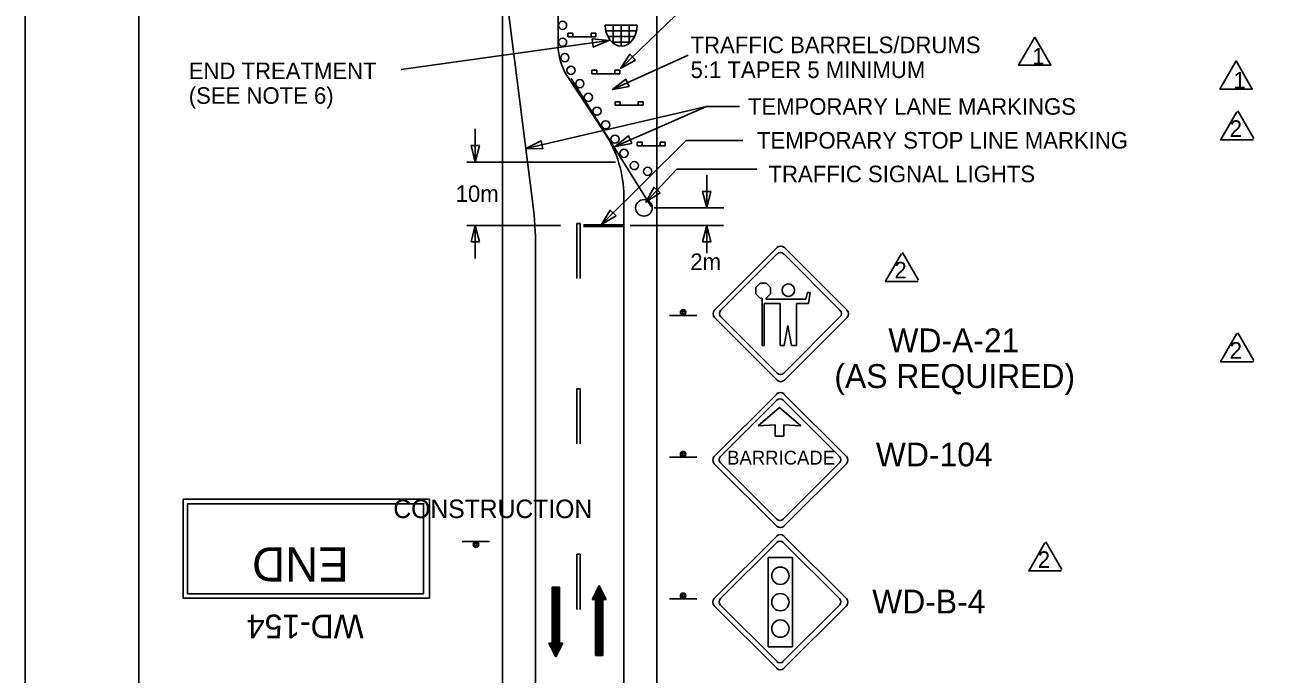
# Model space of a CAD drawing. Extents: x 2179 to 2395, y 134 to 413.
# Drawn here: x 2178.7 to 2288.3, y 251.3 to 308.2 of the extents above; entities that cross this region are included whole.
import ezdxf

# ---------------------------------------------------------------- set-up
doc = ezdxf.new("R2010")
doc.units = 0
for name, color, linetype in [('Level 1', 7, 'Continuous'), ('Level 10', 7, 'Continuous'), ('Level 2', 7, 'Continuous'), ('Level 4', 7, 'Continuous'), ('Level 44', 7, 'Continuous'), ('Level 5', 7, 'Continuous'), ('Level 60', 7, 'Continuous'), ('Level 63', 7, 'Continuous')]:
    doc.layers.add(name, color=color, linetype=linetype)

# ---------------------------------------------------------------- blocks, each defined once
blk = doc.blocks.new('END')
at = {"layer": 'Level 2'}
for points in [[(0, 8.676), (21.598, 8.676), (21.598, 0), (0, 0)], [(0.511, 8.287), (21.224, 8.287), (21.224, 0.397), (0.511, 0.397)]]:
    blk.add_lwpolyline(points, close=True, dxfattribs=at)
at = {"layer": 'Level 44'}
for s, height, rotation, p in [('END', 3, 359.99999, (7.085, 4.219)), ('CONSTRUCTION', 1.62, 179.99999, (3.164, 1.653))]:
    blk.add_text(s, height=height, rotation=rotation, dxfattribs=at).set_placement(p)
blk = doc.blocks.new('REV1')
at = {"layer": 'Level 1'}
blk.add_lwpolyline([(0.114, 1.689), (-1.305, -0.781), (1.533, -0.781)], close=True, dxfattribs=at)
blk.add_text('1', height=1.448, rotation=360, dxfattribs=at).set_placement((-0.113, -0.724))

msp = doc.modelspace()

# ---------------------------------------------------------------- linework, layer by layer
at = {"layer": 'Level 1'}
for p, q in [((2243.25, 285.56), (2242.87, 285.18)), ((2242.87, 285.18), (2242.87, 284.63)), ((2243.79, 285.56), (2243.25, 285.56)), ((2244.17, 285.18), (2243.79, 285.56)), ((2244.17, 284.63), (2244.17, 285.18)), ((2242.87, 284.63), (2243.25, 284.25)), ((2243.25, 284.25), (2243.42, 284.25)), ((2243.42, 284.25), (2243.42, 280.1)), ((2243.79, 284.25), (2244.17, 284.63)), ((2243.79, 284.18), (2243.79, 284.25)), ((2247.27, 284.18), (2243.79, 284.18)), ((2247.41, 284.76), (2247.27, 284.18)), ((2247.65, 284.76), (2247.41, 284.76)), ((2247.49, 283.79), (2247.65, 284.76)), ((2243.61, 280.1), (2243.61, 283.79)), ((2243.61, 283.79), (2245, 283.79)), ((2245, 283.79), (2245, 280.1)), ((2246.44, 280.1), (2246.44, 283.79)), ((2246.44, 283.79), (2247.49, 283.79)), ((2245.36, 280.1), (2245.69, 281.87)), ((2245.69, 281.87), (2246, 280.1)), ((2243.42, 280.1), (2243.61, 280.1)), ((2245, 280.1), (2245.36, 280.1)), ((2246, 280.1), (2246.44, 280.1)), ((2243.95, 261.5), (2246.11, 261.5)), ((2243.95, 253.67), (2243.95, 261.5)), ((2243.95, 253.68), (2243.95, 261.5)), ((2246.11, 261.5), (2246.11, 253.68)), ((2246.11, 253.68), (2243.95, 253.68)), ((2243.95, 253.68), (2243.95, 253.67))]:
    msp.add_line(p, q, dxfattribs=at)
msp.add_circle((2245.73, 284.96), 0.544, dxfattribs=at)
at = {"layer": 'Level 10'}
for p, q in [((2231.01, 304.4), (2256.5, 329.05)), ((2234.19, 178.24), (2234.19, 326.61)), ((2220.64, 178.24), (2220.64, 313.63)), ((2225.53, 313.63), (2225.53, 306.46)), ((2223.31, 292.52), (2221.04, 310.52)), ((2229.99, 306.85), (2211.76, 304.33)), ((2230.29, 302.55), (2236.95, 305.57)), ((2226.35, 303.71), (2229.65, 298.7)), ((2226.66, 303.54), (2233.7, 292.29)), ((2222.7, 297.38), (2238.55, 301.08)), ((2230.53, 297.57), (2238.55, 301.08)), ((2241.46, 301.08), (2238.55, 301.08)), ((2218.26, 299.1), (2218.26, 296.2)), ((2229.33, 290.71), (2236.77, 298.09)), ((2236.77, 298.09), (2241.75, 298.09)), ((2230.56, 296.2), (2217.53, 296.2)), ((2233.22, 292.69), (2235.94, 295.56)), ((2235.94, 295.56), (2242.97, 295.56)), ((2238.57, 295.06), (2238.57, 292.18)), ((2231.29, 178.24), (2231.29, 293.21)), ((2233.95, 292.18), (2240.06, 292.18)), ((2225.73, 290.64), (2217.53, 290.64)), ((2218.26, 287.74), (2218.26, 290.64)), ((2231.29, 290.69), (2227.75, 290.69)), ((2231.29, 290.69), (2227.75, 290.69)), ((2231.29, 290.64), (2227.75, 290.64)), ((2231.29, 290.64), (2227.75, 290.64)), ((2231.29, 290.64), (2227.75, 290.64)), ((2231.29, 290.6), (2227.75, 290.6)), ((2231.29, 290.6), (2227.75, 290.6)), ((2231.29, 290.55), (2227.75, 290.55)), ((2240.04, 290.64), (2231.85, 290.64)), ((2238.57, 290.64), (2238.57, 288.2)), ((2223.55, 178.24), (2223.55, 288.76)), ((2225.02, 254), (2225.02, 258.91)), ((2225.64, 258.91), (2225.02, 258.91)), ((2225.02, 253.39), (2225.02, 258.91)), ((2225.1, 253.24), (2225.1, 258.91)), ((2225.18, 253.08), (2225.18, 258.91)), ((2225.25, 252.93), (2225.25, 258.91)), ((2225.33, 252.78), (2225.33, 258.91)), ((2225.41, 252.93), (2225.41, 258.91)), ((2225.48, 253.08), (2225.48, 258.91)), ((2225.56, 253.24), (2225.56, 258.91)), ((2225.64, 254), (2225.64, 258.91)), ((2225.64, 253.39), (2225.64, 258.91)), ((2229.13, 259.05), (2228.52, 257.82)), ((2228.97, 258.74), (2228.97, 252.91)), ((2229.05, 258.89), (2229.05, 252.91)), ((2229.13, 259.05), (2229.13, 252.91)), ((2229.13, 259.05), (2229.74, 257.82)), ((2229.21, 258.89), (2229.21, 252.91)), ((2229.28, 258.74), (2229.28, 252.91)), ((2228.52, 257.82), (2228.82, 257.82)), ((2228.59, 257.97), (2228.59, 257.82)), ((2228.67, 258.13), (2228.67, 257.82)), ((2228.75, 258.28), (2228.75, 257.82)), ((2228.82, 258.43), (2228.82, 252.91)), ((2228.82, 257.82), (2228.82, 252.91)), ((2228.9, 258.59), (2228.9, 252.91)), ((2229.36, 258.59), (2229.36, 252.91)), ((2229.44, 258.43), (2229.44, 252.91)), ((2229.44, 257.82), (2229.44, 252.91)), ((2229.44, 257.82), (2229.74, 257.82)), ((2229.51, 258.28), (2229.51, 257.82)), ((2229.59, 258.13), (2229.59, 257.82)), ((2229.67, 257.97), (2229.67, 257.82)), ((2225.33, 252.78), (2224.72, 254)), ((2225.02, 254), (2224.72, 254)), ((2224.79, 253.85), (2224.79, 254)), ((2224.87, 253.7), (2224.87, 254)), ((2224.95, 253.54), (2224.95, 254)), ((2225.33, 252.78), (2225.94, 254)), ((2225.94, 254), (2225.64, 254)), ((2225.71, 253.54), (2225.71, 254)), ((2225.79, 253.7), (2225.79, 254)), ((2225.87, 253.85), (2225.87, 254)), ((2228.82, 252.91), (2229.44, 252.91))]:
    msp.add_line(p, q, dxfattribs=at)
for points in [[(2228.51, 307.01), (2229.99, 306.85), (2228.61, 306.29)], [(2232.31, 305.13), (2231.01, 304.4), (2231.81, 305.66)], [(2232, 297.82), (2230.53, 297.57), (2231.71, 298.49)], [(2218.62, 297.65), (2218.26, 296.2), (2217.9, 297.65)], [(2224.19, 297.36), (2222.7, 297.38), (2224.03, 298.06)], [(2234.48, 293.49), (2233.22, 292.69), (2233.95, 293.99)], [(2230.61, 291.48), (2229.33, 290.71), (2230.1, 291.99)], [(2217.9, 289.19), (2218.26, 290.64), (2218.62, 289.19)], [(2238.21, 289.19), (2238.57, 290.64), (2238.93, 289.19)]]:
    msp.add_lwpolyline(points, close=True, dxfattribs=at)
for centre in [(2225.92, 308.19), (2225.92, 306.71), (2226.12, 305.35), (2226.66, 304.24), (2227.44, 303.07), (2228.18, 301.87), (2228.94, 300.66), (2229.7, 299.46), (2230.52, 298.21), (2231.31, 296.96), (2232.21, 295.89), (2233.38, 295.38)]:
    msp.add_circle(centre, 0.359, dxfattribs=at)
msp.add_arc((2221.29, 293.21), 10, 0, 33.3066, dxfattribs=at)
at = {"layer": 'Level 2'}
for p, q in [((2227.17, 290.82), (2227.17, 285.98)), ((2227.46, 290.82), (2227.17, 290.82)), ((2227.46, 285.98), (2227.46, 290.82)), ((2227.17, 276.31), (2227.17, 271.47)), ((2227.46, 276.31), (2227.17, 276.31)), ((2227.46, 271.47), (2227.46, 276.31)), ((2227.17, 261.79), (2227.17, 256.96)), ((2227.46, 261.79), (2227.17, 261.79)), ((2227.46, 256.96), (2227.46, 261.79))]:
    msp.add_line(p, q, dxfattribs=at)
for points in [[(2214.24, 257.94), (2192.64, 257.94), (2192.64, 266.62), (2214.24, 266.62)], [(2213.72, 258.33), (2193.01, 258.33), (2193.01, 266.22), (2213.72, 266.22)]]:
    msp.add_lwpolyline(points, close=True, dxfattribs=at)
at = {"layer": 'Level 4'}
for p, q in [((2229.67, 308.21), (2232.47, 308.21)), ((2230.37, 308.21), (2230.37, 306.61)), ((2231.07, 308.21), (2231.07, 306.37)), ((2231.77, 308.21), (2231.77, 306.61)), ((2229.72, 307.71), (2232.42, 307.71)), ((2229.89, 307.21), (2232.25, 307.21)), ((2230.26, 306.71), (2231.88, 306.71))]:
    msp.add_line(p, q, dxfattribs=at)
msp.add_ellipse((2231.07, 308.22), major_axis=(0, -1.85), ratio=0.758621, start_param=4.716532, end_param=7.849839, dxfattribs=at)
at = {"layer": 'Level 44'}
for p, q in [((2244.74, 288.69), (2239.25, 283.2)), ((2250.88, 283.2), (2245.39, 288.69)), ((2239.8, 283.2), (2244.74, 288.14)), ((2245.33, 288.14), (2250.26, 283.2)), ((2235.29, 282.75), (2237.69, 282.75)), ((2239.25, 282.55), (2244.74, 277.06)), ((2239.25, 282.55), (2239.25, 282.55)), ((2244.74, 277.67), (2239.8, 282.61)), ((2250.26, 282.61), (2245.33, 277.67)), ((2245.39, 277.06), (2250.88, 282.55)), ((2244.71, 275.85), (2239.23, 270.38)), ((2239.78, 270.38), (2244.71, 275.3)), ((2245.29, 275.3), (2250.21, 270.38)), ((2250.82, 270.38), (2245.35, 275.85)), ((2244.95, 274.66), (2243.07, 273.07)), ((2246.83, 273.07), (2244.95, 274.66)), ((2243.07, 273.07), (2244.57, 273.15)), ((2244.57, 273.15), (2244.57, 272.15)), ((2245.33, 272.15), (2245.33, 273.15)), ((2245.33, 273.15), (2246.83, 273.07)), ((2244.57, 272.15), (2245.32, 272.15)), ((2235.29, 270.31), (2237.69, 270.31)), ((2239.23, 269.73), (2244.71, 264.26)), ((2239.23, 269.73), (2239.23, 269.73)), ((2244.71, 264.87), (2239.78, 269.8)), ((2250.21, 269.8), (2245.29, 264.87)), ((2245.35, 264.26), (2250.82, 269.73)), ((2244.71, 263.38), (2239.23, 257.92)), ((2250.82, 257.92), (2245.35, 263.38)), ((2217.12, 262.91), (2219.51, 262.91)), ((2239.78, 257.91), (2244.71, 262.83)), ((2245.29, 262.83), (2250.21, 257.91)), ((2235.29, 257.88), (2237.69, 257.88)), ((2239.23, 257.27), (2244.71, 251.79)), ((2239.23, 257.27), (2239.23, 257.27)), ((2244.71, 252.4), (2239.78, 257.33)), ((2250.21, 257.33), (2245.29, 252.4)), ((2245.35, 251.79), (2250.82, 257.27))]:
    msp.add_line(p, q, dxfattribs=at)
for centre, radius in [((2233.06, 292.18), 0.726), ((2236.5, 283.02), 0.24), ((2236.5, 283.02), 0.12), ((2236.5, 270.58), 0.24), ((2236.5, 270.58), 0.12), ((2218.32, 262.64), 0.24), ((2218.32, 262.64), 0.12), ((2245.03, 259.91), 0.76), ((2236.5, 258.15), 0.24), ((2236.5, 258.15), 0.12), ((2245.03, 257.59), 0.76), ((2245.03, 255.27), 0.76)]:
    msp.add_circle(centre, radius, dxfattribs=at)
for centre, radius, start, end in [((2245.06, 288.37), 0.459, 45, 135), ((2245.03, 287.84), 0.413, 45, 135), ((2239.58, 282.88), 0.459, 135, 225), ((2240.09, 282.9), 0.413, 135, 225), ((2249.97, 282.9), 0.413, 315, 45), ((2250.55, 282.88), 0.459, 315, 45), ((2245.03, 277.97), 0.413, 225, 315), ((2245.06, 277.39), 0.459, 225, 315), ((2245.03, 275.53), 0.458, 45, 135), ((2245, 275.01), 0.412, 45, 135), ((2239.56, 270.06), 0.458, 135, 225), ((2240.07, 270.09), 0.412, 135, 225), ((2249.92, 270.09), 0.412, 315, 45), ((2250.5, 270.06), 0.458, 315, 45), ((2245, 265.16), 0.412, 225, 315), ((2245.03, 264.59), 0.458, 225, 315), ((2245.03, 263.06), 0.458, 45, 135), ((2245, 262.54), 0.412, 45, 135), ((2239.56, 257.59), 0.458, 135, 225), ((2240.07, 257.62), 0.412, 135, 225), ((2249.92, 257.62), 0.412, 315, 45), ((2250.5, 257.59), 0.458, 315, 45), ((2245, 252.69), 0.412, 225, 315), ((2245.03, 252.12), 0.458, 225, 315)]:
    msp.add_arc(centre, radius, start, end, dxfattribs=at)
at = {"layer": 'Level 5'}
for p, q in [((2226.83, 307.5), (2226.39, 307.5)), ((2226.39, 307.5), (2226.39, 307.19)), ((2226.39, 307.19), (2228.85, 307.19)), ((2226.83, 307.19), (2226.83, 307.5)), ((2228.85, 307.5), (2228.42, 307.5)), ((2228.42, 307.5), (2228.42, 307.19)), ((2228.85, 307.19), (2228.85, 307.5)), ((2228.93, 304.25), (2228.49, 304.25)), ((2228.49, 304.25), (2228.49, 303.94)), ((2228.49, 303.94), (2230.95, 303.94)), ((2228.93, 303.94), (2228.93, 304.25)), ((2230.95, 304.25), (2230.51, 304.25)), ((2230.51, 304.25), (2230.51, 303.94)), ((2230.95, 303.94), (2230.95, 304.25)), ((2230.96, 301.48), (2230.53, 301.48)), ((2230.53, 301.48), (2230.53, 301.18)), ((2230.96, 301.18), (2230.96, 301.48)), ((2232.99, 301.48), (2232.55, 301.48)), ((2232.55, 301.48), (2232.55, 301.18)), ((2232.99, 301.18), (2232.99, 301.48)), ((2230.53, 301.18), (2232.99, 301.18)), ((2232.9, 297.94), (2232.47, 297.94)), ((2232.47, 297.94), (2232.47, 297.63)), ((2232.47, 297.63), (2234.93, 297.63)), ((2232.9, 297.63), (2232.9, 297.94)), ((2234.93, 297.94), (2234.49, 297.94)), ((2234.49, 297.94), (2234.49, 297.63)), ((2234.93, 297.63), (2234.93, 297.94))]:
    msp.add_line(p, q, dxfattribs=at)
for points in [[(2231.76, 302.82), (2230.29, 302.55), (2231.46, 303.48)], [(2238.93, 293.63), (2238.57, 292.18), (2238.21, 293.63)]]:
    msp.add_lwpolyline(points, close=True, dxfattribs=at)
for centre, radius, start, end in [((2230.53, 306.46), 5, 180, 213.3066), ((2193.55, 288.76), 30, 0, 7.1968)]:
    msp.add_arc(centre, radius, start, end, dxfattribs=at)
at = {"layer": 'Level 60'}
for points in [[(2394.75, 412.76), (2178.75, 412.76), (2178.75, 133.76), (2394.75, 133.76)], [(2375.62, 401.95), (2188.75, 401.95), (2188.75, 144.57), (2375.62, 144.57)]]:
    msp.add_lwpolyline(points, close=True, dxfattribs=at)
at = {"layer": 'Level 63'}
for points in [[(2285.09, 300.61), (2283.69, 298.18)], [(2286.57, 298.26), (2285.18, 300.69)], [(2283.69, 298.18), (2283.67, 298.14), (2286.51, 298.14), (2286.48, 298.18)], [(2257.15, 285.84), (2255.75, 288.27)], [(2255.66, 288.19), (2254.27, 285.76)], [(2254.27, 285.76), (2254.25, 285.72), (2257.08, 285.72), (2257.06, 285.76)], [(2285.09, 281.15), (2283.69, 278.72)], [(2286.57, 278.8), (2285.18, 281.22)], [(2283.69, 278.72), (2283.67, 278.68), (2286.51, 278.68), (2286.48, 278.72)], [(2268.24, 262.8), (2266.85, 260.37)], [(2269.73, 260.45), (2268.33, 262.88)], [(2266.85, 260.37), (2266.83, 260.33), (2269.66, 260.33), (2269.64, 260.37)]]:
    msp.add_lwpolyline(points, dxfattribs=at)

# ---------------------------------------------------------------- block references
at = {"layer": 'Level 1'}
for p in [(2267.24, 305.47), (2284.9, 303.38)]:
    msp.add_blockref('REV1', p, dxfattribs=at)
at = {"layer": 'Level 2', "rotation": 180}
msp.add_blockref('END', (2214.24, 266.62), dxfattribs=at)

# ---------------------------------------------------------------- texts
at = {"layer": 'Level 10'}
for s, height, p in [('TRAFFIC BARRELS/DRUMS ', 1.4514, (2237.15, 305.75)), ('END TREATMENT', 1.45, (2193.12, 303.48)), ('5:1 TAPER 5 MINIMUM', 1.4514, (2237.15, 303.57)), ('(SEE NOTE 6)', 1.45, (2193.12, 301.31)), ('TEMPORARY LANE MARKINGS', 1.451, (2242.18, 300.35)), ('TEMPORARY STOP LINE MARKING', 1.451, (2242.98, 297.38)), ('TRAFFIC SIGNAL LIGHTS', 1.451, (2243.99, 294.43)), ('10m', 1.451, (2216.54, 292.7)), ('2m', 1.451, (2237.13, 286.73)), ('WD-A-21', 2.09, (2254.51, 279.51)), ('(AS REQUIRED)', 2.09, (2249.77, 276.38)), ('WD-104', 2.09, (2253.41, 269.5)), ('WD-B-4', 2.09, (2253.09, 256.6))]:
    msp.add_text(s, height=height, dxfattribs=at).set_placement(p)
msp.add_text('WD-154', height=2.09, rotation=180, dxfattribs=at).set_placement((2208.47, 256.5))
at = {"layer": 'Level 44'}
for s, height, p in [('2', 1.45, (2284.46, 298.41)), ('2', 1.45, (2255.04, 285.99)), ('2', 1.45, (2284.46, 278.95)), ('BARRICADE', 1.214, (2240.36, 269.66)), ('CONSTRUCTION', 1.6202, (2211.07, 264.97)), ('2', 1.45, (2267.62, 260.6))]:
    msp.add_text(s, height=height, rotation=360, dxfattribs=at).set_placement(p)

doc.saveas('drawing.dxf')
